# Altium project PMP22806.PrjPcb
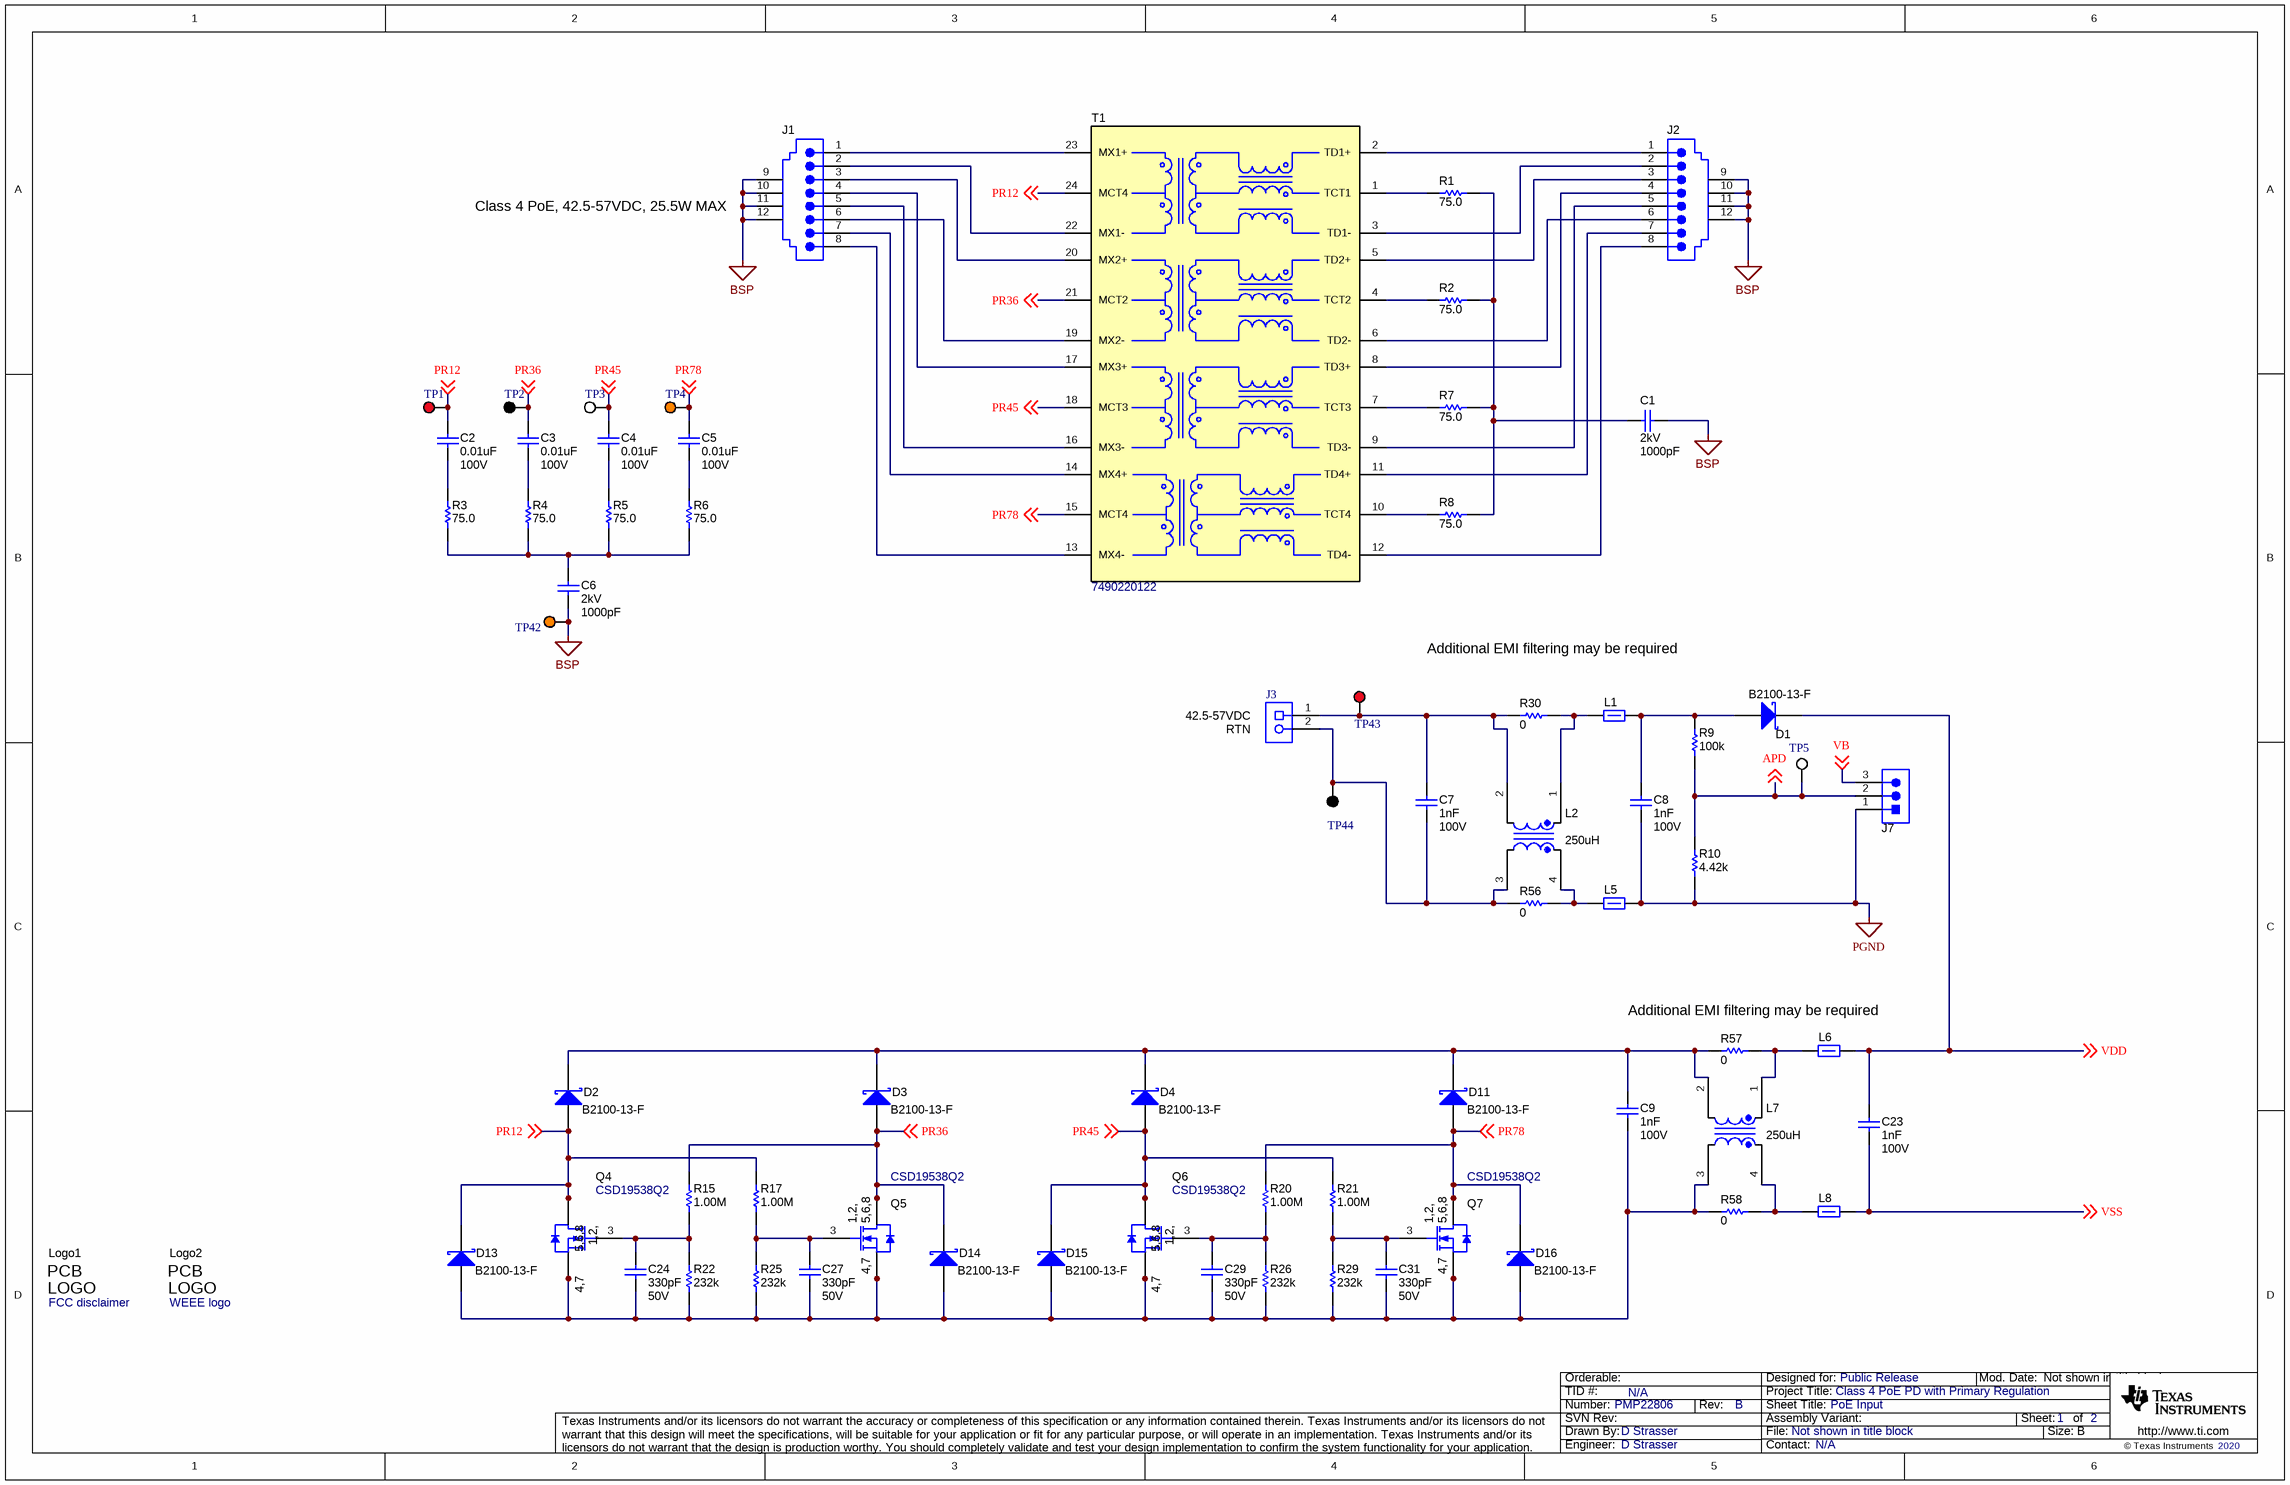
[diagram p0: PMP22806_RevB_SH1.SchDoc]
CopyrightYear: 2020; PCB_Layout: D Strasser; PCB_Rev: B; PRJ_Customer: Public Release; PRJ_Engineer: D Strasser; PRJ_Number: PMP22806; PRJ_Title: Class 4 PoE PD with Primary Regulation; SCH_Rev: B; TechSupport: N/A; TID: N/A
2 sheets, 196 parts. Net scope: global (net labels, ports and power ports of the same name join across sheets).
Board file: PMP22806_RevB.PcbDoc
Sheets:
  PMP22806_RevB_SH1.SchDoc
  PMP22806_RevB_SH2.SchDoc

## Sheet PMP22806_RevB_SH1.SchDoc: PoE Input
size 431 x 279 mm; Date: Not shown in title block; ApprovedBy: Not shown in title block; CheckedBy: Not shown in title block; Author: Not shown in title block; CompanyName: Not shown in title block; DrawnBy: D Strasser; Engineer: Not shown in title block; Organization: Not shown in title block; Address1: Not shown in title block; Address2: Not shown in title block; Address3: Not shown in title block; Address4: Not shown in title block; DocumentNumber: 1; Revision: Use project parameter SCH_Rev; SheetNumber: 1; SheetTotal: 2; PageSetup: Record=PageOptions¦CenterHorizontal=True¦CenterVertical=True¦PrintScale=1.00¦XCorrection=1.00¦YCorrection=1.00¦PrintKind=0¦BorderSize=5000000¦LeftOffset=0¦BottomOffset=0¦Orientation=2¦PaperLength=1000¦PaperWidth=1000¦Scale=100¦PaperSource=15¦PrintQuality=600¦MediaType=1¦DitherType=10¦PaperKind=Letter¦PrintScaleMode=1

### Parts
C1  VDC_V: 2kV  ValueDisplayed: 1000pF  [1812]  (hidden comment: GR443QR73D102KW01L)
C2  ValueDisplayed: 0.01uF  Value2: 100V  [0603L]  (hidden comment: Capacitor)
C3  ValueDisplayed: 0.01uF  Value2: 100V  [0603L]  (hidden comment: Capacitor)
C4  ValueDisplayed: 0.01uF  Value2: 100V  [0603L]  (hidden comment: Capacitor)
C5  ValueDisplayed: 0.01uF  Value2: 100V  [0603L]  (hidden comment: Capacitor)
C6  VDC_V: 2kV  ValueDisplayed: 1000pF  [1812]  (hidden comment: GR443QR73D102KW01L)
C7  Cap_F: 1nF  VDC_V: 100V  [0603]  (hidden comment: C1608X7R2A102K080AA)
C8  Cap_F: 1nF  VDC_V: 100V  [0603]  (hidden comment: C1608X7R2A102K080AA)
C9  Cap_F: 1nF  VDC_V: 100V  [0603]  (hidden comment: C1608X7R2A102K080AA)
C23  Cap_F: 1nF  VDC_V: 100V  [0603]  (hidden comment: C1608X7R2A102K080AA)
C24  ValueDisplayed: 330pF  VDC_V: 50V  [0603]  (hidden comment: GRM1885C1H331JA01D)
C27  ValueDisplayed: 330pF  VDC_V: 50V  [0603]  (hidden comment: GRM1885C1H331JA01D)
C29  ValueDisplayed: 330pF  VDC_V: 50V  [0603]  (hidden comment: GRM1885C1H331JA01D)
C31  ValueDisplayed: 330pF  VDC_V: 50V  [0603]  (hidden comment: GRM1885C1H331JA01D)
D1  PartNumber: B2100-13-F  [SMB]  (hidden comment: CMP-0028397-2)
D2  PartNumber: B2100-13-F  [SMB]  (hidden comment: CMP-0028397-2)
D3  PartNumber: B2100-13-F  [SMB]  (hidden comment: CMP-0028397-2)
D4  PartNumber: B2100-13-F  [SMB]  (hidden comment: CMP-0028397-2)
D11  PartNumber: B2100-13-F  [SMB]  (hidden comment: CMP-0028397-2)
D13  PartNumber: B2100-13-F  [SMB]  (hidden comment: CMP-0028397-2)
D14  PartNumber: B2100-13-F  [SMB]  (hidden comment: CMP-0028397-2)
D15  PartNumber: B2100-13-F  [SMB]  (hidden comment: CMP-0028397-2)
D16  PartNumber: B2100-13-F  [SMB]  (hidden comment: CMP-0028397-2)
J1  1-406541-1  [TEC_1-406541-1]  (value not drawn)
J2  1-406541-1  [TEC_1-406541-1]  (value not drawn)
J3  ED555/2DS  [TERM_BLK_ED555-2DS]  (value not drawn)
J7  TSW-103-07-G-S  [TSW-103-07-G-S]  (value not drawn)
L1  CMP-0003192-2  [0603]  (value not drawn)
L2  ValueDisplayed: 250uH  [WE-SL5]  (hidden comment: 744272251)
L5  CMP-0003192-2  [0603]  (value not drawn)
L6  CMP-0003192-2  [0603]  (value not drawn)
L7  ValueDisplayed: 250uH  [WE-SL5]  (hidden comment: 744272251)
L8  CMP-0003192-2  [0603]  (value not drawn)
Logo1  FCC disclaimer  [FCC_disclaimer]  (no BOM)
Logo2  WEEE logo  [WEEE_Minimum]  (no BOM)
Q4  CSD19538Q2  [DQK0006C]
Q5  CSD19538Q2  [DQK0006C]
Q6  CSD19538Q2  [DQK0006C]
Q7  CSD19538Q2  [DQK0006C]
R1  ValueDisplayed: 75.0  [0603L]  (hidden comment: Resistor)
R2  ValueDisplayed: 75.0  [0603L]  (hidden comment: Resistor)
R3  ValueDisplayed: 75.0  [0603L]  (hidden comment: Resistor)
R4  ValueDisplayed: 75.0  [0603L]  (hidden comment: Resistor)
R5  ValueDisplayed: 75.0  [0603L]  (hidden comment: Resistor)
R6  ValueDisplayed: 75.0  [0603L]  (hidden comment: Resistor)
R7  ValueDisplayed: 75.0  [0603L]  (hidden comment: Resistor)
R8  ValueDisplayed: 75.0  [0603L]  (hidden comment: Resistor)
R9  ValueDisplayed: 100k  [0603]  (hidden comment: CRCW0603100KFKEA)
R10  ValueDisplayed: 4.42k  [0603]  (hidden comment: CRCW06034K42FKEA)
R15  ValueDisplayed: 1.00M  [0603]  (hidden comment: CMP-0022138-4)
R17  ValueDisplayed: 1.00M  [0603]  (hidden comment: CMP-0022138-4)
R20  ValueDisplayed: 1.00M  [0603]  (hidden comment: CMP-0022138-4)
R21  ValueDisplayed: 1.00M  [0603]  (hidden comment: CMP-0022138-4)
R22  ValueDisplayed: 232k  [0603]  (hidden comment: CMP-0022224-4)
R25  ValueDisplayed: 232k  [0603]  (hidden comment: CMP-0022224-4)
R26  ValueDisplayed: 232k  [0603]  (hidden comment: CMP-0022224-4)
R29  ValueDisplayed: 232k  [0603]  (hidden comment: CMP-0022224-4)
R30  ValueDisplayed: 0  [0603]  (hidden comment: ERJ-3GEY0R00V)
R56  ValueDisplayed: 0  [0603]  (hidden comment: ERJ-3GEY0R00V)
R57  ValueDisplayed: 0  [0603]  (hidden comment: ERJ-3GEY0R00V)
R58  ValueDisplayed: 0  [0603]  (hidden comment: ERJ-3GEY0R00V)
T1  7490220122  [Wurth_7490220122]
TP1  5000  [Keystone5000]  (value not drawn)
TP2  5001  [Keystone5001]  (value not drawn)
TP3  5002  [Keystone5002]  (value not drawn)
TP4  5003  [Keystone5003]  (value not drawn)
TP5  5002  [Keystone5002]  (value not drawn)
TP42  5003  [Keystone5003]  (value not drawn)
TP43  5000  [Keystone5000]  (value not drawn)
TP44  5001  [Keystone5001]  (value not drawn)

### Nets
BSP: C1.1 C6.2 J1.9 J1.10 J1.11 J1.12 J2.9 J2.10 J2.11 J2.12 TP42.1
PGND: C8.2 J7.1 L5.2 R10.1
APD: J7.2 R9.1 R10.2 TP5.1 ; off-sheet APD
PR12: C2.1 D2.2(A) D13.1(K) Q4.1(D) Q4.2(D) Q4.5(D) Q4.6(D) Q4.8(D) R17.2 T1.24(MCT4) TP1.1 ; off-sheet PR12
PR36: C3.1 D3.2(A) D14.1(K) Q5.1(D) Q5.2(D) Q5.5(D) Q5.6(D) Q5.8(D) R15.2 T1.21(MCT2) TP2.1 ; off-sheet PR36
PR45: C4.1 D4.2(A) D15.1(K) Q6.1(D) Q6.2(D) Q6.5(D) Q6.6(D) Q6.8(D) R21.2 T1.18(MCT3) TP3.1 ; off-sheet PR45
PR78: C5.1 D11.2(A) D16.1(K) Q7.1(D) Q7.2(D) Q7.5(D) Q7.6(D) Q7.8(D) R20.2 T1.15(MCT4) TP4.1 ; off-sheet PR78
VB: J7.3 ; off-sheet VB
VDD: C23.1 D1.1(K) L6.2 ; off-sheet VDD
VSS: C23.2 L8.2 ; off-sheet VSS
NetC1_2: C1.2 R1.2 R2.2 R7.2 R8.1
NetC2_2: C2.2 R3.2
NetC3_2: C3.2 R4.2
NetC4_2: C4.2 R5.2
NetC5_2: C5.2 R6.2
NetC6_1: C6.1 R3.1 R4.1 R5.1 R6.1
NetC7_1: C7.1 J3.1 L2.2 R30.1 TP43.1
NetC7_2: C7.2 J3.2 L2.3 R56.1 TP44.1
NetC8_1: C8.1 D1.2(A) L1.2 R9.2
NetC9_1: C9.1 D2.1(K) D3.1(K) D4.1(K) D11.1(K) L7.2 R57.1
NetC9_2: C9.2 C24.2 C27.2 C29.2 C31.2 D13.2(A) D14.2(A) D15.2(A) D16.2(A) L7.3 Q4.4(S) Q4.7(S) Q5.4(S) Q5.7(S) Q6.4(S) Q6.7(S) Q7.4(S) Q7.7(S) R22.1 R25.1 R26.1 R29.1 R58.1
NetC24_1: C24.1 Q4.3(G) R15.1 R22.2
NetC27_1: C27.1 Q5.3(G) R17.1 R25.2
NetC29_1: C29.1 Q6.3(G) R20.1 R26.2
NetC31_1: C31.1 Q7.3(G) R21.1 R29.2
NetJ1_1: J1.1 T1.23(MX1+)
NetJ1_2: J1.2 T1.22(MX1-)
NetJ1_3: J1.3 T1.20(MX2+)
NetJ1_4: J1.4 T1.17(MX3+)
NetJ1_5: J1.5 T1.16(MX3-)
NetJ1_6: J1.6 T1.19(MX2-)
NetJ1_7: J1.7 T1.14(MX4+)
NetJ1_8: J1.8 T1.13(MX4-)
NetJ2_1: J2.1 T1.2(TD1+)
NetJ2_2: J2.2 T1.3(TD1-)
NetJ2_3: J2.3 T1.5(TD2+)
NetJ2_4: J2.4 T1.8(TD3+)
NetJ2_5: J2.5 T1.9(TD3-)
NetJ2_6: J2.6 T1.6(TD2-)
NetJ2_7: J2.7 T1.11(TD4+)
NetJ2_8: J2.8 T1.12(TD4-)
NetL1_1: L1.1 L2.1 R30.2
NetL2_4: L2.4 L5.1 R56.2
NetL6_1: L6.1 L7.1 R57.2
NetL7_4: L7.4 L8.1 R58.2
NetR1_1: R1.1 T1.1(TCT1)
NetR2_1: R2.1 T1.4(TCT2)
NetR7_1: R7.1 T1.7(TCT3)
NetR8_2: R8.2 T1.10(TCT4)

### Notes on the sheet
- Class 4 PoE, 42.5-57VDC, 25.5W MAX
- Additional EMI filtering may be required
- (near J3) 42.5-57VDC
- (near J3) RTN

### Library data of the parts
C1 C6 = CMP-0009438-2: CAP, CERM, 1000 pF, 2000 V, +/- 10%, X7R, 1812; Manufacturer: MuRata; TaMin_C: -55°C; Polarized: N; SizeAreaWB_mm2: 23.1; Value1: Unknown; U/M: EA; Value: 1000pF; TaMax_C: 125°C; SizeZ_mm: 1.35; SizeX_mm: 4.5; SizeY_mm: 3.2; Value2: 2000V; SizeArea_mm2: 14.4; Cap_F: 1nF; AEC Category: Q200
C2-C5 = CMP-0007468-5: CAP, CERM, 0.01 uF, 100 V, +/- 10%, X7R, 0603; PartNumber: GRM188R72A103KA01D; Manufacturer: MuRata; Polarized: N; Value: 0.01uF; U/M: EA; Cap_F: 10nF; Value1: Unknown; TaMin_C: -55°C; TaMax_C: 125°C; Cap_Case: 0603; SizeArea_mm2: 1.28; SizeAreaWB_mm2: 4.68; SizeX_mm: 1.6; SizeY_mm: 0.8; SizeZ_mm: 1; AEC Category: Q200
C7-C9 C23 = CMP-0007053-4: CAP, CERM, 1000 pF, 100 V, +/- 10%, X7R, 0603; Manufacturer: TDK; Polarized: N; Value: 1000pF; U/M: EA; Value1: Unknown; TaMin_C: -55°C; TaMax_C: 125°C; SizeAreaWB_mm2: 4.68; SizeZ_mm: 1; SizeX_mm: 1.6; SizeY_mm: 0.8; SizeArea_mm2: 1.28; AEC Category: Q200
C24 C27 C29 C31 = CMP-0007209-4: CAP, CERM, 330 pF, 50 V, +/- 5%, C0G/NP0, 0603; Manufacturer: MuRata; Polarized: N; Value: 330pF; U/M: EA; Value1: Unknown; TaMin_C: -55°C; TaMax_C: 125°C; AEC Category: Q200; SizeAreaWB_mm2: 4.68; SizeZ_mm: 1; SizeX_mm: 1.6; SizeY_mm: 0.8; SizeArea_mm2: 1.28
D1-D4 D11 D13-D16 = CMP-0028397-2: Diode, Schottky, 100 V, 2 A, SMB; Manufacturer: Diodes Inc.; Vf_V: 790mV; Value: 100V; Value1: 2A; Value2: 0.79V; TJmax_C: 150°C; RJC_CperW: 15; SizeArea_mm2: 21.336; Green_REACh: Passed; Green_Lifecycle: Active; SizeY_mm: 3.81; AEC Category: Q101; SizeZ_mm: 2.6; SizeAreaWB_mm2: 44.156; SizeX_mm: 5.6
J1 J2 = CMP-0054918-1: RJ45, No LED, tab up, R/A, TH; Manufacturer: TE Connectivity; CNHeader: FALSE; Green_Lifecycle: Active; Green_REACh: Passed; ContactFinish: Gold; CT: TRUE
J3 = CMP-0074913-1: Terminal Block, 3.5mm Pitch, 2x1, TH; Manufacturer: On-Shore Technology; Cert_VDE: Y; CNHeader: False; Current_A: 6A; Green_Lifecycle: Active; Shrouded: N; Gender: Female; Green_REACh: Passed; Voltage_V: 150V; Row_Count: 1; Pitch_mm: 3.5; ContactFinish: Brass; CT: True
J7 = CMP-0075407-2: Header, 100mil, 3x1, Gold, TH; Manufacturer: Samtec; Pitch_mm: 2.54; Cert_VDE: N; Gender: Male; Cert_CSA: Y; Voltage_V: 550V; Green_REACh: Passed; Current_A: 6.3A; Green_Lifecycle: Active; Row_Count: 1
L1 L5 L6 L8 = CMP-0003192-2: Ferrite Bead, 300 ohm @ 100 MHz, 2 A, 0603; PartNumber: 742792641; Manufacturer: Wurth Elektronik; Value: 300 ohm; Imax_A: 2A; DCR_ohm: 0.15; Value1: 0.15 ohm; ZTyp@100MHz_Ohm: 300; Ztyp@1GHz_Ohm: 273.989; SizeAreaWB_mm2: 4.68; SizeZ_mm: 1; SizeX_mm: 1.6; SizeY_mm: 0.8; SizeArea_mm2: 1.28
L2 L7 = CMP-0013220-2: Coupled inductor, 250 uH,  A, 0.035 ohm, SMD; Manufacturer: Wurth Elektronik; DCR_ohm: 0.035; Value: 250uH; Ind_H: 250µH
Logo1 = CMP-0074847-1: FCC_disclaimer
Logo2 = CMP-0074769-1
Q4-Q7 = CMP-0000968-2: MOSFET, N-CH, 100 V, 4.5 A, DQK0006C (WSON-6); Alternate Manufacturer: None; Manufacturer: Texas Instruments; SizeZ_mm: 0.8; ChType: N; VdsMax_V: 100V; SizeX_mm: 2; SizeAreaWB_mm2: 9; Vgs_V: 20V; Value: 100V; SizeArea_mm2: 4; AEC Category: Q101; IdsMax_A: 4.5A; U/M: EA
R1-R8 = CMP-0022590-4: RES, 75.0, 1%, 0.1 W, AEC-Q200 Grade 0, 0603; PartNumber: CRCW060375R0FKEA; Manufacturer: Vishay-Dale; Value: 75.0; Res_ohm: 75; Value_Code: 75R0; Power_W: 100mW; Value2: 0.1W; VDC_V: 75V; TempCo: 100 ppm/C; SizeArea_mm2: 1.28; SizeX_mm: 1.6; SizeY_mm: 0.8; SizeZ_mm: 1; EIA_Code: E96; AEC Category: Q200; AEC Qualified: Y; AEC Grade: 0
R9 = CMP-0021990-4: RES, 100 k, 1%, 0.1 W, AEC-Q200 Grade 0, 0603; Manufacturer: Vishay-Dale; Power_W: 100mW; TempCo: 100 ppm/C; Value: 100k; EIA_Code: E96; SizeX_mm: 1.6; SizeY_mm: 0.8; SizeZ_mm: 1; Value2: 0.1W; SizeArea_mm2: 1.28; AEC Qualified: Y; VDC_V: 75V; AEC Category: Q200; AEC Grade: 0
R10 = CMP-0022453-4: RES, 4.42 k, 1%, 0.1 W, AEC-Q200 Grade 0, 0603; Manufacturer: Vishay-Dale; Power_W: 100mW; TempCo: 100 ppm/C; Value_Code: 4k42; Value: 4.42k; EIA_Code: E96; SizeX_mm: 1.6; SizeY_mm: 0.8; SizeZ_mm: 1; Value2: 0.1W; SizeArea_mm2: 1.28; AEC Qualified: Y; VDC_V: 75V; AEC Category: Q200; AEC Grade: 0
R15 R17 R20 R21 = CMP-0022138-4: RES, 1.00 M, 1%, 0.1 W, AEC-Q200 Grade 0, 0603; PartNumber: CRCW06031M00FKEA; Manufacturer: Vishay-Dale; Value: 1.00Meg; Res_ohm: 1M; Value_Code: 1M00; Power_W: 100mW; Value2: 0.1W; VDC_V: 75V; TempCo: 100 ppm/C; EIA_Code: E96; AEC Category: Q200; AEC Qualified: Y; AEC Grade: 0; SizeX_mm: 1.6; SizeY_mm: 0.8; SizeZ_mm: 1; SizeArea_mm2: 1.28
R22 R25 R26 R29 = CMP-0022224-4: RES, 232 k, 1%, 0.1 W, AEC-Q200 Grade 0, 0603; PartNumber: CRCW0603232KFKEA; Manufacturer: Vishay-Dale; Value: 232k; Power_W: 100mW; Value2: 0.1W; VDC_V: 75V; TempCo: 100 ppm/C; EIA_Code: E96; AEC Category: Q200; AEC Qualified: Y; AEC Grade: 0; SizeX_mm: 1.6; SizeY_mm: 0.8; SizeZ_mm: 1; SizeArea_mm2: 1.28
R30 R56-R58 = CMP-0025874-4: RES, 0, 5%, 0.1 W, AEC-Q200 Grade 0, 0603; Manufacturer: Panasonic; Power_W: 100mW; TempCo: 600 ppm/C; Value_Code: 0000; Value: 0; EIA_Code: E24; SizeX_mm: 1.6; SizeY_mm: 0.8; SizeZ_mm: 1; Value2: 0.1W; SizeArea_mm2: 1.28; AEC Qualified: Y; VDC_V: 50V; AEC Category: Q200; SizeAreaWB_mm2: 4.68
T1 = CMP-0030597-1: Transformer, 350 uH, SMT; Manufacturer: Wurth Elektronik; Value: 350uH; Ind_H: 350µH; Lp: 350
TP1 TP43 = CMP-0055137-1: Test Point, Miniature, Red, TH; Manufacturer: Keystone; CNHeader: FALSE; Green_Lifecycle: Active; Green_REACh: Passed; ContactFinish: Silver; CT: TRUE
TP2 TP44 = CMP-0055138-1: Test Point, Miniature, Black, TH; Manufacturer: Keystone; CNHeader: FALSE; Green_Lifecycle: Active; Green_REACh: Passed; ContactFinish: Silver; CT: TRUE
TP3 TP5 = CMP-0055139-1: Test Point, Miniature, White, TH; Manufacturer: Keystone; CNHeader: FALSE; Green_Lifecycle: Active; Green_REACh: Passed; ContactFinish: Silver; CT: TRUE
TP4 TP42 = CMP-0055140-1: Test Point, Miniature, Orange, TH; Manufacturer: Keystone; CNHeader: FALSE; Green_Lifecycle: Active; Green_REACh: Passed; ContactFinish: Silver; CT: TRUE

## Sheet PMP22806_RevB_SH2.SchDoc: Flyback Converter
size 431 x 279 mm; Date: Not shown in title block; ApprovedBy: Not shown in title block; CheckedBy: Not shown in title block; Author: Not shown in title block; CompanyName: Not shown in title block; DrawnBy: D Strasser; Engineer: Not shown in title block; Organization: Not shown in title block; Address1: Not shown in title block; Address2: Not shown in title block; Address3: Not shown in title block; Address4: Not shown in title block; DocumentNumber: 2; Revision: Use project parameter SCH_Rev; SheetNumber: 2; SheetTotal: 2; PageSetup: Record=PageOptions¦CenterHorizontal=True¦CenterVertical=True¦PrintScale=1.00¦XCorrection=1.00¦YCorrection=1.00¦PrintKind=0¦BorderSize=5000000¦LeftOffset=0¦BottomOffset=0¦Orientation=2¦PaperLength=1000¦PaperWidth=1000¦Scale=100¦PaperSource=15¦PrintQuality=600¦MediaType=1¦DitherType=10¦PaperKind=Letter¦PrintScaleMode=1
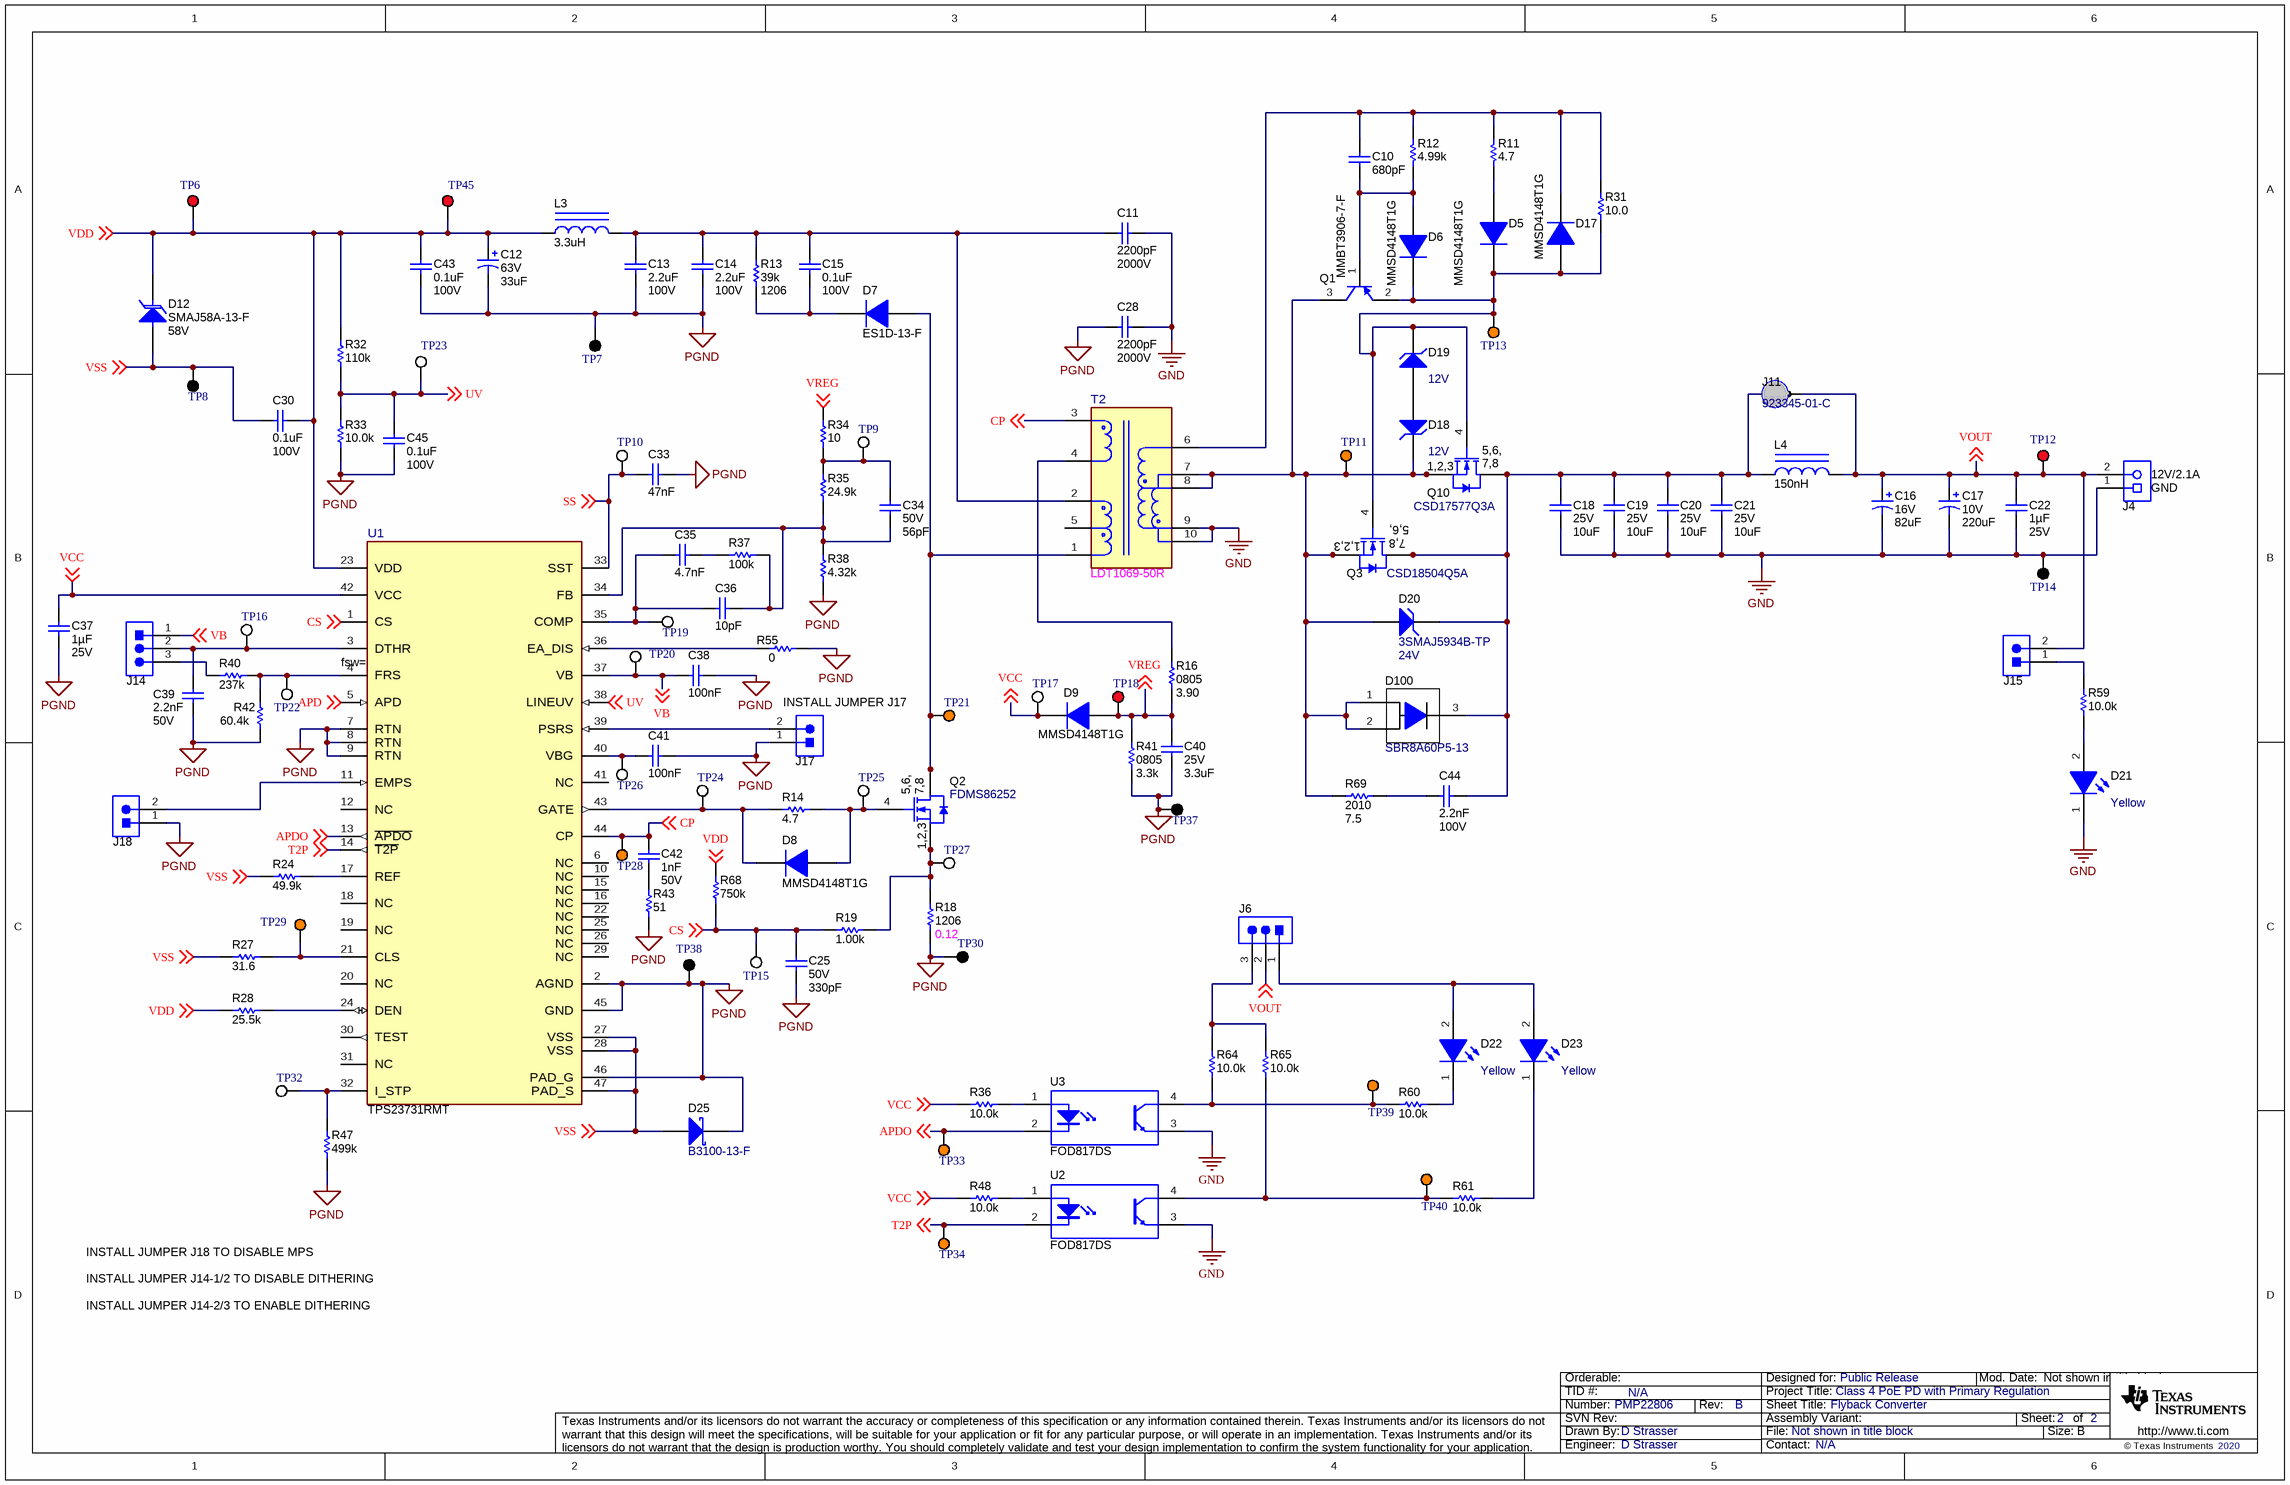
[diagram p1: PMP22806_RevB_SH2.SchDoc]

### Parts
C10  ValueDisplayed: 680pF  [0603L]  (hidden comment: GRM188R71H681KA01D)
C11  ValueDisplayed: 2200pF  Value2: 2000V  [1812_HV]  (hidden comment: Capacitor)
C12  VDC_V: 63V  ValueDisplayed: 33uF  [SM_RADIAL_F]  (hidden comment: EEE-FK1J330P)
C13  ValueDisplayed: 2.2uF  Value2: 100V  [1210_270]  (hidden comment: Capacitor)
C14  ValueDisplayed: 2.2uF  Value2: 100V  [1210_270]  (hidden comment: Capacitor)
C15  ValueDisplayed: 0.1uF  Value2: 100V  [0805_HV]  (hidden comment: Capacitor)
C16  VDC_V: 16V  ValueDisplayed: 82uF  [SM_RADIAL_8MM]  (hidden comment: 16SVP82M)
C17  VDC_V: 10V  ValueDisplayed: 220uF  [7343-30]  (hidden comment: 10TPE220ML)
C18  VDC_V: 25V  ValueDisplayed: 10uF  [1210_220]  (hidden comment: 885012209028)
C19  VDC_V: 25V  ValueDisplayed: 10uF  [1210_220]  (hidden comment: 885012209028)
C20  VDC_V: 25V  ValueDisplayed: 10uF  [1210_220]  (hidden comment: 885012209028)
C21  VDC_V: 25V  ValueDisplayed: 10uF  [1210_220]  (hidden comment: 885012209028)
C22  Cap_F: 1µF  VDC_V: 25V  [0603]  (hidden comment: 885012206076)
C25  VDC_V: 50V  ValueDisplayed: 330pF  [0603]  (hidden comment: GRM1885C1H331JA01D)
C28  ValueDisplayed: 2200pF  Value2: 2000V  [1812_HV]  (hidden comment: Capacitor)
C30  ValueDisplayed: 0.1uF  Value2: 100V  [0805_HV]  (hidden comment: Capacitor)
C33  Cap_F: 47nF  [0603]  (hidden comment: GRM188R71E473KA01D)
C34  VDC_V: 50V  ValueDisplayed: 56pF  [0603]  (hidden comment: 06035A560FAT2A)
C35  Cap_F: 4.7nF  [0603]  (hidden comment: 885012206087)
C36  ValueDisplayed: 10pF  [0603]  (hidden comment: 06035A100JAT2A)
C37  Cap_F: 1µF  VDC_V: 25V  [0603]  (hidden comment: 885012206076)
C38  Cap_F: 100nF  [0603]  (hidden comment: 885012206071)
C39  Cap_F: 2.2nF  VDC_V: 50V  [0603]  (hidden comment: C0603C222K5RAC)
C40  VDC_V: 25V  ValueDisplayed: 3.3uF  [1206_180]  (hidden comment: GRM31CR71E335KA88L)
C41  Cap_F: 100nF  [0603]  (hidden comment: 885012206071)
C42  Cap_F: 1nF  VDC_V: 50V  [0603]  (hidden comment: 885012206083)
C43  ValueDisplayed: 0.1uF  Value2: 100V  [0805_HV]  (hidden comment: Capacitor)
C44  Cap_F: 2.2nF  VDC_V: 100V  [0603]  (hidden comment: 06031C222KAT2A)
C45  ValueDisplayed: 0.1uF  Value2: 100V  [0805_HV]  (hidden comment: Capacitor)
D5  MMSD4148T1G  [SOD-123]
D6  MMSD4148T1G  [SOD-123]
D7  ES1D-13-F  [SMA]
D8  MMSD4148T1G  [SOD-123]
D9  MMSD4148T1G  [SOD-123]
D12  SMAJ58A-13-F  value 58V  [SMA]
D17  MMSD4148T1G  [SOD-123]
D18  value 12V  [SOD-123]  (hidden comment: MMSZ5242B-7-F)
D19  value 12V  [SOD-123]  (hidden comment: MMSZ5242B-7-F)
D20  3SMAJ5934B-TP  value 24V  [SMA]
D21  value Yellow  [WL-SMCW_YELLOW]  (hidden comment: 150060YS75000)
D22  value Yellow  [WL-SMCW_YELLOW]  (hidden comment: 150060YS75000)
D23  value Yellow  [WL-SMCW_YELLOW]  (hidden comment: 150060YS75000)
D25  B3100-13-F  [SMC]
D100  SBR8A60P5-13  [POWERDI5]
J4  Receptacle_2x1  [TERM_BLK_ED555-2DS]  (value not drawn)
J6  TSW-103-07-G-S  [TSW-103-07-G-S]  (value not drawn)
J11  923345-01-C  [3M_923345-01-C]
J14  TSW-103-07-G-S  [TSW-103-07-G-S]  (value not drawn)
J15  TSW-102-07-G-S  [TSW-102-07-G-S]  (value not drawn)
J17  TSW-102-07-G-S  [TSW-102-07-G-S]  (value not drawn)
J18  TSW-102-07-G-S  [TSW-102-07-G-S]  (value not drawn)
L3  ValueDisplayed: 3.3uH  [WE-TPC-M1]  (hidden comment: 744042003)
L4  ValueDisplayed: 150nH  [WE-HCM_7050]  (hidden comment: 744302015)
Q1  MMBT3906-7-F  [SOT-23L]
Q2  FDMS86252  [TRANS_Fairchild_PQFN08A]
Q3  CSD18504Q5A  [DQJ0008A]
Q10  CSD17577Q3A  [DNH0008A]
R11  ValueDisplayed: 4.7  [0603L]  (hidden comment: Resistor)
R12  ValueDisplayed: 4.99k  [0603L]  (hidden comment: CRCW06034K99FKEA)
R13  ValueDisplayed: 39k  PackageReference: 1206  [1206L]  (hidden comment: Resistor)
R14  ValueDisplayed: 4.7  [0603]  (hidden comment: CRCW06034R70JNEA)
R16  PackageReference: 0805  ValueDisplayed: 3.90  [0805_HV]  (hidden comment: ERJ-6RQF3R9V)
R18  ValueDisplayed: 0.12  [1206]  (hidden comment: ERJ-8RQFR12V)
R19  ValueDisplayed: 1.00k  [0603]  (hidden comment: RC0603FR-071KL)
R24  ValueDisplayed: 49.9k  [0603]  (hidden comment: CRCW060349K9FKEA)
R27  ValueDisplayed: 31.6  [0805_HV]  (hidden comment: CRCW080531R6FKEA)
R28  ValueDisplayed: 25.5k  [0603]  (hidden comment: RC0603FR-0725K5L)
R31  ValueDisplayed: 10.0  [0603]  (hidden comment: CRCW060310R0FKEA)
R32  ValueDisplayed: 110k  [0603]  (hidden comment: CRCW0603110KFKEA)
R33  ValueDisplayed: 10.0k  [0603L]  (hidden comment: CRCW060310K0FKEA)
R34  ValueDisplayed: 10  [0603]  (hidden comment: CRCW060310R0JNEA)
R35  ValueDisplayed: 24.9k  [0603]  (hidden comment: RC0603FR-0724K9L)
R36  ValueDisplayed: 10.0k  [0603L]  (hidden comment: CRCW060310K0FKEA)
R37  ValueDisplayed: 100k  [0603]  (hidden comment: CRCW0603100KFKEA)
R38  ValueDisplayed: 4.32k  [0603]  (hidden comment: CRCW06034K32FKEA)
R40  ValueDisplayed: 237k  [0603]  (hidden comment: RC0603FR-07237KL)
R41  PackageReference: 0805  ValueDisplayed: 3.3k  [0805_HV]  (hidden comment: CRCW08053K30JNEA)
R42  ValueDisplayed: 60.4k  [0603]  (hidden comment: CRCW060360K4FKEA)
R43  ValueDisplayed: 51  [1206]  (hidden comment: CRCW120651R0JNEA)
R47  ValueDisplayed: 499k  [0603]  (hidden comment: CRCW0603499KFKEA)
R48  ValueDisplayed: 10.0k  [0603L]  (hidden comment: CRCW060310K0FKEA)
R55  ValueDisplayed: 0  [0603]  (hidden comment: ERJ-3GEY0R00V)
R59  ValueDisplayed: 10.0k  [0603L]  (hidden comment: CRCW060310K0FKEA)
R60  ValueDisplayed: 10.0k  [0603L]  (hidden comment: CRCW060310K0FKEA)
R61  ValueDisplayed: 10.0k  [0603L]  (hidden comment: CRCW060310K0FKEA)
R64  ValueDisplayed: 10.0k  [0603L]  (hidden comment: CRCW060310K0FKEA)
R65  ValueDisplayed: 10.0k  [0603L]  (hidden comment: CRCW060310K0FKEA)
R68  ValueDisplayed: 750k  [0603]  (hidden comment: CRCW0603750KFKEA)
R69  ValueDisplayed: 7.5  [2010]  (hidden comment: CRCW20107R50JNEF)
T2  PartNumber: LDT1069-50R  [FP-LDT1038-50R_SMD10-MFG]  (hidden comment: LDT1038-50R)
TP6  5000  [Keystone5000]  (value not drawn)
TP7  5001  [Keystone5001]  (value not drawn)
TP8  5001  [Keystone5001]  (value not drawn)
TP9  5002  [Keystone5002]  (value not drawn)
TP10  5002  [Keystone5002]  (value not drawn)
TP11  5003  [Keystone5003]  (value not drawn)
TP12  5000  [Keystone5000]  (value not drawn)
TP13  5003  [Keystone5003]  (value not drawn)
TP14  5001  [Keystone5001]  (value not drawn)
TP15  5002  [Keystone5002]  (value not drawn)
TP16  5002  [Keystone5002]  (value not drawn)
TP17  5002  [Keystone5002]  (value not drawn)
TP18  5000  [Keystone5000]  (value not drawn)
TP19  5002  [Keystone5002]  (value not drawn)
TP20  5002  [Keystone5002]  (value not drawn)
TP21  5003  [Keystone5003]  (value not drawn)
TP22  5002  [Keystone5002]  (value not drawn)
TP23  5002  [Keystone5002]  (value not drawn)
TP24  5002  [Keystone5002]  (value not drawn)
TP25  5002  [Keystone5002]  (value not drawn)
TP26  5002  [Keystone5002]  (value not drawn)
TP27  5002  [Keystone5002]  (value not drawn)
TP28  5003  [Keystone5003]  (value not drawn)
TP29  5003  [Keystone5003]  (value not drawn)
TP30  5001  [Keystone5001]  (value not drawn)
TP32  5002  [Keystone5002]  (value not drawn)
TP33  5003  [Keystone5003]  (value not drawn)
TP34  5003  [Keystone5003]  (value not drawn)
TP37  5001  [Keystone5001]  (value not drawn)
TP38  5001  [Keystone5001]  (value not drawn)
TP39  5003  [Keystone5003]  (value not drawn)
TP40  5003  [Keystone5003]  (value not drawn)
TP45  5000  [Keystone5000]  (value not drawn)
U1  TPS23731RMT  [RMT0045A-MFG]
U2  FOD817DS  [N04C]
U3  FOD817DS  [N04C]

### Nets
GND: C11.1 C16.2(-) C17.2(-) C18.2 C19.2 C20.2 C21.2 C22.2 C28.1 D21.1(K) J4.1 T2.9 T2.10 TP14.1 U2.3(E) U3.3(E)
PGND: C12.2(-) C13.2 C14.2 C25.2 C28.2 C33.1 C37.2 C38.1 C39.2 C40.2 C41.1 C43.2 C45.1 D25.1(K) J17.1 J18.1 R18.2 R33.2 R38.2 R41.1 R42.1 R43.1 R47.1 R55.2 TP7.1 TP30.1 TP37.1 TP38.1 U1.2(AGND) U1.7(RTN) U1.8(RTN) U1.9(RTN) U1.45(GND) U1.46(PAD_G)
APD: U1.5(APD) ; off-sheet APD
APDO: TP33.1 U1.13(~{APDO}) U3.2(K) ; off-sheet APDO
CP: C42.1 T2.3 TP28.1 U1.44(CP) ; off-sheet CP
CS: C25.1 R19.1 R68.2 TP15.1 U1.1(CS) ; off-sheet CS
SS: C33.2 TP10.1 U1.33(SST) ; off-sheet SS
T2P: TP34.1 U1.14(~{T2P}) U2.2(K) ; off-sheet T2P
UV: C45.2 R32.1 R33.1 TP23.1 U1.38(LINEUV) ; off-sheet UV
VB: C38.2 J14.1 TP20.1 U1.37(VB) ; off-sheet VB
VCC: C37.1 D9.1(K) R36.2 R48.2 TP17.1 U1.42(VCC) ; off-sheet VCC
VDD: C12.1(+) C30.1 C43.1 D12.1(K) L3.1 R28.1 R32.2 R68.1 TP6.1 TP45.1 U1.23(VDD) ; off-sheet VDD
VOUT: C16.1(+) C17.1(+) C22.1 J4.2 J6.2 J11.2 J15.2 L4.2 TP12.1 ; off-sheet VOUT
VREG: C40.1 D9.2(A) R16.1 R34.1 R41.2 TP18.1 ; off-sheet VREG
VSS: C30.2 D12.2(A) D25.2(A) R24.1 R27.1 TP8.1 U1.27(VSS) U1.28(VSS) U1.47(PAD_S) ; off-sheet VSS
NetC10_1: C10.1 D17.1(K) R11.1 R12.2 R31.2 T2.6
NetC10_2: C10.2 D6.2(A) Q1.1(B) R12.1
NetC11_2: C11.2 C13.1 C14.1 C15.2 L3.2 R13.2 T2.2
NetC15_1: C15.1 D7.1(K) R13.1
NetC18_1: C18.1 C19.1 C20.1 C21.1 C44.1 D20.1(K) D100.3(K) J11.1 L4.1 Q3.5(D) Q3.6(D) Q3.7(D) Q3.8(D) Q3.9(D) Q10.5(D) Q10.6(D) Q10.7(D) Q10.8(D) Q10.9(D)
NetC34_1: C34.1 R34.2 R35.2 TP9.1
NetC34_2: C34.2 C36.1 R35.1 R37.2 R38.1 U1.34(FB)
NetC35_1: C35.1 R37.1
NetC35_2: C35.2 C36.2 TP19.1 U1.35(COMP)
NetC39_1: C39.1 J14.2 TP16.1 U1.3(DTHR)
NetC41_2: C41.2 TP26.1 U1.40(VBG)
NetC42_2: C42.2 R43.2
NetC44_2: C44.2 R69.2
NetD5_1: D5.1(K) D6.1(K) D17.2(A) D19.1(K) Q1.2(E) Q3.4(G) Q10.4(G) R31.1 TP13.1
NetD5_2: D5.2(A) R11.2
NetD7_2: D7.2(A) Q2.5(D) Q2.6(D) Q2.7(D) Q2.8(D) T2.1 TP21.1
NetD8_1: D8.1(K) R14.1 TP24.1 U1.43(GATE)
NetD8_2: D8.2(A) Q2.4(G) R14.2 TP25.1
NetD18_1: D18.1(K) D20.2(A) D100.1(A) D100.2(A) Q1.3(C) Q3.1(S) Q3.2(S) Q3.3(S) Q10.1(S) Q10.2(S) Q10.3(S) R69.1 T2.7 T2.8 TP11.1
NetD18_2: D18.2(A) D19.2(A)
NetD21_2: D21.2(A) R59.1
NetD22_1: D22.1(K) R60.2
NetD22_2: D22.2(A) D23.2(A) J6.1
NetD23_1: D23.1(K) R61.2
NetJ6_3: J6.3 R64.2 R65.2
NetJ14_3: J14.3 R40.1
NetJ15_1: J15.1 R59.2
NetJ17_2: J17.2 U1.39(PSRS)
NetJ18_2: J18.2 U1.11(EMPS)
NetQ2_1: Q2.1(S) Q2.2(S) Q2.3(S) R18.1 R19.2 TP27.1
NetR16_2: R16.2 T2.4
NetR24_2: R24.2 U1.17(REF)
NetR27_2: R27.2 TP29.1 U1.21(CLS)
NetR28_2: R28.2 U1.24(DEN)
NetR36_1: R36.1 U3.1(A)
NetR40_2: R40.2 R42.2 TP22.1 U1.4(FRS)
NetR47_2: R47.2 TP32.1 U1.32(I_STP)
NetR48_1: R48.1 U2.1(A)
NetR55_1: R55.1 U1.36(EA_DIS)
NetR60_1: R60.1 R64.1 TP39.1 U3.4(C)
NetR61_1: R61.1 R65.1 TP40.1 U2.4(C)

Not connected (* = marked no-connect by the designer): T2 5; U1 6(NC) 10(NC) 12(NC) 15(NC) 16(NC) 18(NC) 19(NC) 20(NC) 22(NC) 25(NC) 26(NC) 29(NC) 30(TEST) 31(NC) 41(NC)

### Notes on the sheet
- (near J4) GND
- (near J4) 12V/2.1A
- fsw=250KHz
- (near J17) INSTALL JUMPER J17
- INSTALL JUMPER J18 TO DISABLE MPS
- INSTALL JUMPER J14-1/2 TO DISABLE DITHERING
- INSTALL JUMPER J14-2/3 TO ENABLE DITHERING

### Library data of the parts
C10 = CMP-0007461-4: CAP, CERM, 680 pF, 50 V, +/- 10%, X7R, 0603; Manufacturer: MuRata; TaMin_C: -55°C; Polarized: N; SizeAreaWB_mm2: 4.68; Value1: Unknown; U/M: EA; Value: 680pF; TaMax_C: 125°C; SizeZ_mm: 1; SizeX_mm: 1.6; SizeY_mm: 0.8; Cap_Case: 0603; Value2: 50V; SizeArea_mm2: 1.28; CompType: Capacitor; AEC Category: Q200
C11 C28 = CMP-0009358-2: CAP, CERM, 2200 pF, 2000 V, +/- 10%, X7R, 1812; PartNumber: C4532X7R3D222K130KA; Manufacturer: TDK; Polarized: N; Value: 2200pF; U/M: EA; Cap_F: 2.2nF; Value1: Unknown; VDC_V: 2kV; TaMin_C: -55°C; TaMax_C: 125°C; Cap_Case: 1812; SizeArea_mm2: 14.4; SizeAreaWB_mm2: 23.1; SizeX_mm: 4.5; SizeY_mm: 3.2; SizeZ_mm: 1.35; AEC Category: Q200
C12 = CMP-0011191-2: CAP, AL, 33 uF, 63 V, +/- 20%, 0.65 ohm, AEC-Q200 Grade 2, SMD; Manufacturer: Panasonic; TaMin_C: -55°C; ESR_ohm: 0.65; Polarized: Y; SizeAreaWB_mm2: 123.6; U/M: EA; Value: 33uF; TaMax_C: 105°C; SizeZ_mm: 10.2; SizeX_mm: 10; SizeY_mm: 8.3; Cap_Case: F; SizeArea_mm2: 83; CompType: Capacitor; Cap_F: 33µF; IRMS_A: 250mA; AEC Grade: 2; AEC Category: Q200
C13 C14 = CMP-0009232-2: CAP, CERM, 2.2 uF, 100 V, +/- 10%, X7R, 1210; PartNumber: GRM32ER72A225KA35L; Manufacturer: MuRata; Polarized: N; Value: 2.2uF; U/M: EA; Cap_F: 2.2µF; ESR_ohm: 7m; Value1: 0.007 ohm; IRMS_A: 4.4A; TaMin_C: -55°C; TaMax_C: 125°C; Cap_Case: 1210; SizeArea_mm2: 8; SizeAreaWB_mm2: 14.7; SizeX_mm: 3.2; SizeY_mm: 2.5; SizeZ_mm: 2.7; AEC Category: Q200
C15 C30 C43 C45 = CMP-0007886-2: CAP, CERM, 0.1 uF, 100 V, +/- 10%, X7R, 0805; PartNumber: C2012X7R2A104K125AA; Manufacturer: TDK; Polarized: N; Value: 0.1uF; U/M: EA; Cap_F: 100nF; ESR_ohm: 0.020726; Value1: 0.020726 ohm; IRMS_A: 1.456A; TaMin_C: -55°C; TaMax_C: 125°C; Cap_Case: 0805; SizeArea_mm2: 2.5; SizeAreaWB_mm2: 6.75; SizeX_mm: 2; SizeY_mm: 1.25; SizeZ_mm: 1.45; AEC Category: Q200
C16 = CMP-0012087-3: CAP, Aluminum Polymer, 82 uF, 16 V, +/- 20%, 0.04 ohm, 8x10 SMD; Manufacturer: Panasonic; TaMin_C: -55°C; ESR_ohm: 0.04; Polarized: Y; SizeAreaWB_mm2: 113.3; Value: 82uF; TaMax_C: 105°C; SizeZ_mm: 10.2; SizeX_mm: 9; SizeY_mm: 8.3; Cap_Case: 8.3x8.3x6.9; SizeArea_mm2: 74.7; CompType: Capacitor; Cap_F: 82µF; IRMS_A: 2.12A; AEC Category: Q200
C17 = CMP-0012611-3: CAP, Tantalum Polymer, 220 uF, 10 V, +/- 20%, 0.025 ohm, 7343-30 SMD; Manufacturer: Panasonic; TaMin_C: -55°C; ESR_ohm: 0.025; Polarized: Y; SizeAreaWB_mm2: 58.59; Value: 220uF; TaMax_C: 105°C; SizeZ_mm: 3; SizeX_mm: 7.3; SizeY_mm: 4.3; SizeArea_mm2: 31.39; CompType: Capacitor; AEC Qualified: N; Cap_F: 220µF; IRMS_A: 2.4A; AEC Category: Q200
C18-C21 = CMP-0064938-2: CAP, CERM, 10 uF, 25 V,+/- 10%, X7R, 1210; Manufacturer: Wurth Elektronik; TaMin_C: -55°C; Polarized: N; SizeAreaWB_mm2: 14.7; Value1: Unknown; U/M: EA; Value: 10uF; TaMax_C: 125°C; SizeZ_mm: 2.2; SizeX_mm: 3.2; SizeY_mm: 2.5; Cap_Case: 1210; SizeArea_mm2: 8; Cap_F: 10µF; AEC Category: Q200
C22 C37 = CMP-0006833-4: CAP, CERM, 1 uF, 25 V, +/- 10%, X7R, 0603; Manufacturer: Wurth Elektronik; TaMin_C: -55°C; Polarized: N; SizeAreaWB_mm2: 4.68; Value1: Unknown; U/M: EA; Value: 1uF; TaMax_C: 125°C; SizeZ_mm: 1; SizeX_mm: 1.6; SizeY_mm: 0.8; SizeArea_mm2: 1.28; AEC Category: Q200
C25 = CMP-0007209-4: CAP, CERM, 330 pF, 50 V, +/- 5%, C0G/NP0, 0603; Manufacturer: MuRata; TaMin_C: -55°C; Polarized: N; SizeAreaWB_mm2: 4.68; Value1: Unknown; U/M: EA; Value: 330pF; TaMax_C: 125°C; SizeZ_mm: 1; SizeX_mm: 1.6; SizeY_mm: 0.8; SizeArea_mm2: 1.28; AEC Category: Q200
C33 = CMP-0007423-5: CAP, CERM, 0.047 uF, 25 V, +/- 10%, X7R, 0603; Manufacturer: MuRata; Polarized: N; SizeArea_mm2: 1.28; Value2: 25V; TaMax_C: 125°C; SizeZ_mm: 1; Value1: Unknown; SizeAreaWB_mm2: 4.68; TaMin_C: -55°C; AEC Category: Q200; SizeY_mm: 0.8; MFG_Status: TI_Obsolete; SizeX_mm: 1.6; U/M: EA
C34 = CMP-0006792-4: CAP, CERM, 56 pF, 50 V, +/- 1%, C0G/NP0, 0603; Manufacturer: AVX; TaMin_C: -55°C; Polarized: N; SizeAreaWB_mm2: 4.68; Value1: Unknown; U/M: EA; Value: 56pF; TaMax_C: 125°C; SizeZ_mm: 1; SizeX_mm: 1.6; SizeY_mm: 0.8; SizeArea_mm2: 1.28; AEC Category: Q200
C35 = CMP-0006835-4: CAP, CERM, 4700 pF, 50 V, +/- 10%, X7R, 0603; Manufacturer: Wurth Elektronik; TaMin_C: -55°C; Polarized: N; SizeAreaWB_mm2: 4.68; Value1: Unknown; U/M: EA; Value: 4700pF; TaMax_C: 125°C; SizeZ_mm: 1; SizeX_mm: 1.6; SizeY_mm: 0.8; Value2: 50V; SizeArea_mm2: 1.28; AEC Category: Q200
C36 = CMP-0006761-4: CAP, CERM, 10 pF, 50 V, +/- 5%, C0G/NP0, 0603; Manufacturer: AVX; TaMin_C: -55°C; ESR_ohm: 0.403; Polarized: N; SizeAreaWB_mm2: 4.68; Value1: 0.403 ohm; U/M: EA; Value: 10pF; TaMax_C: 125°C; SizeZ_mm: 1; SizeX_mm: 1.6; SizeY_mm: 0.8; Value2: 50V; SizeArea_mm2: 1.28; AEC Category: Q200
C38 C41 = CMP-0006832-5: CAP, CERM, 0.1 uF, 25 V, +/- 10%, X7R, 0603; Manufacturer: Wurth Elektronik; TaMin_C: -55°C; Polarized: N; SizeAreaWB_mm2: 4.68; Value1: Unknown; U/M: EA; Value: 0.1uF; TaMax_C: 125°C; SizeZ_mm: 1; SizeX_mm: 1.6; SizeY_mm: 0.8; Value2: 25V; SizeArea_mm2: 1.28; AEC Category: Q200
C39 = CMP-0006897-4: CAP, CERM, 2200 pF, 50 V, +/- 10%, X7R, 0603; Manufacturer: Kemet; TaMin_C: -55°C; Polarized: N; SizeAreaWB_mm2: 4.68; Value1: Unknown; U/M: EA; Value: 2200pF; TaMax_C: 125°C; SizeZ_mm: 1; SizeX_mm: 1.6; SizeY_mm: 0.8; SizeArea_mm2: 1.28; AEC Category: Q200
C40 = CMP-0008966-2: CAP, CERM, 3.3 uF, 25 V, +/- 10%, X7R, 1206; Manufacturer: MuRata; TaMin_C: -55°C; Polarized: N; SizeAreaWB_mm2: 10.92; Value1: Unknown; U/M: EA; Value: 3.3uF; TaMax_C: 125°C; SizeZ_mm: 1.8; SizeX_mm: 3.2; SizeY_mm: 1.6; Cap_Case: 1206; SizeArea_mm2: 5.12; Cap_F: 3.3µF; AEC Category: Q200
C42 = CMP-0064933-4: CAP, CERM, 1000 pF, 50 V,+/- 10%, X7R, 0603; Manufacturer: Wurth Elektronik; TaMin_C: -55°C; Polarized: N; SizeAreaWB_mm2: 4.68; Value1: Unknown; U/M: EA; Value: 1000pF; TaMax_C: 125°C; SizeZ_mm: 1; SizeX_mm: 1.6; SizeY_mm: 0.8; SizeArea_mm2: 1.28; AEC Category: Q200
C44 = CMP-0006737-4: CAP, CERM, 2200 pF, 100 V, +/- 10%, X7R, 0603; Manufacturer: AVX; TaMin_C: -55°C; ESR_ohm: 0.192; Polarized: N; SizeAreaWB_mm2: 4.68; Value1: 0.192 ohm; U/M: EA; Value: 2200pF; TaMax_C: 125°C; SizeZ_mm: 1; SizeX_mm: 1.6; SizeY_mm: 0.8; SizeArea_mm2: 1.28; AEC Category: Q200
D5 D6 D8 D9 D17 = CMP-0029032-2: Diode, Switching, 100 V, 0.2 A, SOD-123; Manufacturer: ON Semiconductor; Vf_V: 1V; Value: 100V; Value1: 0.2A; Io_A: 200mA; TJmax_C: 150°C; SizeAreaWB_mm2: 13.095; SizeArea_mm2: 6.545; SizeX_mm: 3.85; SizeY_mm: 1.7; SizeZ_mm: 1.35; AEC Category: Q101; Green_Lifecycle: Active; Green_REACh: Passed
D7 = CMP-0029024-2: Diode, Ultrafast, 200 V, 1 A, SMA; Manufacturer: Diodes Inc.; Vf_V: 920mV; Value: 200V; Value1: 1A; Value2: 0.92V; TJmax_C: 150°C; RJC_CperW: 25; SizeAreaWB_mm2: 37.3428; SizeArea_mm2: 16.3228; SizeX_mm: 5.59; SizeY_mm: 2.92; SizeZ_mm: 2.87; AEC Category: Q101; Green_Lifecycle: Active; Green_REACh: Passed
D12 = CMP-0005486-3: Diode, TVS, Uni, 58 V, SMA; Manufacturer: Diodes Inc.; Value1: 400W; SizeAreaWB_mm2: 37.3428; SizeArea_mm2: 16.3228; SizeX_mm: 5.59; SizeY_mm: 2.92; SizeZ_mm: 2.87; AEC Category: Q101
D18 D19 = CMP-0005751-4: Diode, Zener, 12 V, 500 mW, SOD-123; Manufacturer: Diodes Inc.; RJA_CperW: 350; SizeZ_mm: 1.35; SizeAreaWB_mm2: 13.095; AEC Category: Q101; SizeArea_mm2: 6.545; Power_W: 500mW; Value1: 0.5W; SizeY_mm: 1.7; SizeX_mm: 3.85
D20 = CMP-0005513-4: Diode, Zener, 24 V, 3 W, SMA; Manufacturer: Micro Commercial Components; SizeZ_mm: 2.87; Power_W: 3W; SizeAreaWB_mm2: 37.3428; AEC Category: Q101; SizeX_mm: 5.59; SizeArea_mm2: 16.3228; RJA_CperW: 226; SizeY_mm: 2.92
D21-D23 = CMP-0002892-3: LED, Yellow, SMD; Manufacturer: Wurth Elektronik; Value1: W; Vf_V: 2V; Type: AlInGaP; Io_A: 20mA
D25 = CMP-0028411-2: Diode, Schottky, 100 V, 3 A, SMC; Manufacturer: Diodes Inc.; SizeZ_mm: 2.6; Vf_V: 790mV; RJC_CperW: 10; Value2: 0.79V; Io_A: 3A; SizeAreaWB_mm2: 83.2686; SizeY_mm: 6.22; Green_REACh: Passed; TJmax_C: 125°C; SizeX_mm: 8.13; AEC Category: Q101; SizeArea_mm2: 50.5686; Value: 100V; Green_Lifecycle: Active
D100 = CMP-0029276-2: Diode, Super Barrier Rectifier, 60 V, 8 A, PowerDI5; Manufacturer: Diodes Inc.; TJmax_C: 175°C; RJC_CperW: 5; SizeX_mm: 6.4; Value: 60V; SizeArea_mm2: 24.96; Green_REACh: Incomplete; AEC Category: Q101; Vf_V: 620mV; SizeAreaWB_mm2: 49.56; Value2: 0.62V; SizeZ_mm: 1.05; Green_Lifecycle: Not Set; Value1: 8A; SizeY_mm: 3.9
J4 = CMP-0074913-1: Terminal Block, 3.5mm Pitch, 2x1, TH; PartNumber: ED555/2DS; Manufacturer: On-Shore Technology; Pitch_mm: 3.5; Gender: Female; Shrouded: N; Row_Count: 1; ContactFinish: Brass; Current_A: 6A; Voltage_V: 150V; Cert_CULUS: Y; CNHeader: False; CT: True; Green_Lifecycle: Active; Green_REACh: Passed
J6 J14 = CMP-0075407-2: as J7 on sheet PMP22806_RevB_SH1
J11 = CMP-0075087-1: Jumper Wire, 100mil spacing, pkg of 200, TH; Manufacturer: 3M; CNHeader: False; Green_Lifecycle: Active; Green_REACh: Passed
J15 J17 J18 = CMP-0075405-3: Header, 100mil, 2x1, Gold, TH; Manufacturer: Samtec; Current_A: 6.3A; Green_Lifecycle: Active; Pitch_mm: 2.54; Cert_CSA: Y; Cert_VDE: N; Green_REACh: Passed; Row_Count: 1; Gender: Male; Voltage_V: 550V
L3 = CMP-0063798-1: Inductor, Shielded Drum Core, Ferrite, 3.3 uH, 1.8 A, 0.055 ohm, SMD; Manufacturer: Wurth Elektronik; Isat: 1.8A @ 35% inductance drop; Irms: 1.95A @ 30C rise; Green_Lifecycle: Active; SizeAreaWB_mm2: 33.64; DCR_ohm: 0.055; Green_REACh: Passed; Value: 3.3uH; Imax_A: 1.8A; SizeZ_mm: 1.8; SizeX_mm: 4.8; SizeArea_mm2: 23.04; Ind_H: 3.3µH; AEC Category: Q200
L4 = CMP-0063890-1: Inductor, Shielded Drum Core, Ferrite, 150 nH, 30 A, 0.000235 ohm, SMD; Manufacturer: Wurth Elektronik; Isat: 32A @ 20% inductance drop; Irms: 30A @ 50C rise; Green_Lifecycle: Active; SizeAreaWB_mm2: 81; DCR_ohm: 235µ; Green_REACh: Passed; Value: 150nH; Imax_A: 30A; SizeZ_mm: 5; SizeX_mm: 7; SizeArea_mm2: 49; AEC Category: Q200
Q1 = CMP-0000326-2: Transistor, PNP, 40 V, 0.2 A, SOT-23; Manufacturer: Diodes Inc.; CompType: BJT; PNP: 1; NPN: 0; Vceo_V: 40V; Vcesat1_V: 2.5dV; Value: 40 V; IcRated_A: 2dA; Value1: 0.2 A; HfeMax: 400; TaMin_C: -55°C; TaMax_C: 150°C; U/M: EA; AEC Category: Q101; SizeArea_mm2: 7.5; SizeAreaWB_mm2: 14; SizeX_mm: 2.5; SizeY_mm: 3; SizeZ_mm: 1.1
Q2 = CMP-0001058-1: MOSFET, N-CH, 150 V, 4.6 A, PQFN08A; Alternate Manufacturer: None; Manufacturer: Fairchild Semiconductor; SizeZ_mm: 1.1; ChType: N; Value2: 11 nC; Value1: 0; VdsMax_V: 150V; SizeX_mm: 5; SizeY_mm: 6; Vgs_V: 20V; Value: 150V; Rdson45_ohm: 0.07; SizeArea_mm2: 30; AEC Category: Q101; IdsMax_A: 4.6A; SizeAreaWB_mm2: 56; U/M: EA; QgTyp_nC: 11
Q3 = CMP-0000708-1: MOSFET, N-CH, 40 V, 15 A, DQJ0008A (VSONP-8); Alternate Manufacturer: None; Manufacturer: Texas Instruments; SizeZ_mm: 1.1; ChType: N; Value2: 7.7 nC; Value1: 0.009; VdsMax_V: 40V; SizeX_mm: 6; SizeY_mm: 4.9; Vgs_V: 20V; Value: 40V; Rdson45_ohm: 9.8m; SizeArea_mm2: 29.4; AEC Category: Q101; IdsMax_A: 15A; SizeAreaWB_mm2: 55.2; U/M: EA; QgTyp_nC: 7.7
Q10 = CMP-0000589-2: MOSFET, N-CH, 30 V, 19 A, DNH0008A (VSONP-8); Alternate Manufacturer: None; Manufacturer: Texas Instruments; SizeZ_mm: 0.9; ChType: N; Value2: 13 nC; Value1: 0.006; VdsMax_V: 30V; SizeX_mm: 3.3; Vgs_V: 20V; Value: 30V; Rdson45_ohm: 6.4m; SizeArea_mm2: 10.89; AEC Category: Q101; IdsMax_A: 19A; SizeAreaWB_mm2: 18.49; QgTyp_nC: 13; ChMode: Enhancement
R11 = CMP-0025821-4: RES, 4.7, 5%, 0.1 W, AEC-Q200 Grade 0, 0603; PartNumber: CRCW06034R70JNEA; Manufacturer: Vishay-Dale; Value: 4.7; Value_Code: 4R70; Power_W: 100mW; Value2: 0.1W; VDC_V: 75V; TempCo: 200 ppm/C; SizeArea_mm2: 1.28; SizeX_mm: 1.6; SizeY_mm: 0.8; SizeZ_mm: 1; EIA_Code: E24; AEC Category: Q200; AEC Qualified: Y; AEC Grade: 0
R12 = CMP-0022458-4: RES, 4.99 k, 1%, 0.1 W, AEC-Q200 Grade 0, 0603; Manufacturer: Vishay-Dale; Power_W: 100mW; TempCo: 100 ppm/C; Value_Code: 4k99; Value: 4.99k; EIA_Code: E96; SizeX_mm: 1.6; SizeY_mm: 0.8; SizeZ_mm: 1; Value2: 0.1W; SizeArea_mm2: 1.28; CompType: Resistor; AEC Qualified: Y; VDC_V: 75V; AEC Category: Q200; AEC Grade: 0
R13 = CMP-0018666-3: RES, 39 k, 5%, 0.25 W, AEC-Q200 Grade 0, 1206; PartNumber: CRCW120639K0JNEA; Manufacturer: Vishay-Dale; Value: 39k; Value_Code: 39k0; Power_W: 250mW; Value2: 0.25W; VDC_V: 200V; TempCo: 200 ppm/C; SizeArea_mm2: 5.12; SizeX_mm: 3.2; SizeY_mm: 1.6; SizeZ_mm: 1.35; EIA_Code: E24; AEC Category: Q200; AEC Qualified: Y; AEC Grade: 0
R14 = CMP-0025821-4: RES, 4.7, 5%, 0.1 W, AEC-Q200 Grade 0, 0603; Manufacturer: Vishay-Dale; Power_W: 100mW; TempCo: 200 ppm/C; Value_Code: 4R70; Value: 4.7; EIA_Code: E24; SizeX_mm: 1.6; SizeY_mm: 0.8; SizeZ_mm: 1; Value2: 0.1W; SizeArea_mm2: 1.28; AEC Qualified: Y; VDC_V: 75V; AEC Category: Q200; AEC Grade: 0
R16 = CMP-0021831-3: RES, 3.90, 1%, 0.125 W, AEC-Q200 Grade 0, 0805; Manufacturer: Panasonic; Power_W: 125mW; TempCo: 200 ppm/C; Value_Code: 3R90; Value: 3.90; Res_ohm: 3.9; SizeX_mm: 2; SizeY_mm: 1.25; SizeZ_mm: 1.45; Value2: 0.125W; SizeArea_mm2: 2.5; AEC Qualified: Y; AEC Category: Q200; AEC Grade: 0; SizeAreaWB_mm2: 6.75
R18 = CMP-0017789-3: RES, 0.12, 1%, 0.25 W, AEC-Q200 Grade 0, 1206; Manufacturer: Panasonic; Power_W: 250mW; TempCo: 250 ppm/C; Value_Code: R390; Value: 0.12; EIA_Code: E96; Res_ohm: 0.39; SizeX_mm: 3.2; SizeY_mm: 1.6; SizeZ_mm: 1.35; Value2: 0.25W; SizeArea_mm2: 5.12; AEC Qualified: Y; AEC Category: Q200; AEC Grade: 0; SizeAreaWB_mm2: 10.92
R19 = CMP-0022895-5: RES, 1.00 k, 1%, 0.1 W, 0603; Manufacturer: Yageo; Power_W: 100mW; TempCo: 100 ppm/C; Value_Code: 1k00; Value: 1.00k; EIA_Code: E96; Res_ohm: 1k; SizeX_mm: 1.6; SizeY_mm: 0.8; SizeZ_mm: 1; Value2: 0.1W; SizeArea_mm2: 1.28; AEC Qualified: N; VDC_V: 75V; AEC Category: Q200; SizeAreaWB_mm2: 4.68
R24 = CMP-0022447-4: RES, 49.9 k, 1%, 0.1 W, AEC-Q200 Grade 0, 0603; Manufacturer: Vishay-Dale; Power_W: 100mW; TempCo: 100 ppm/C; Value_Code: 49k9; Value: 49.9k; EIA_Code: E96; SizeX_mm: 1.6; SizeY_mm: 0.8; SizeZ_mm: 1; Value2: 0.1W; SizeArea_mm2: 1.28; AEC Qualified: Y; VDC_V: 75V; AEC Category: Q200; AEC Grade: 0
R27 = CMP-0021169-3: RES, 31.6, 1%, 0.125 W, AEC-Q200 Grade 0, 0805; Manufacturer: Vishay-Dale; Power_W: 125mW; TempCo: 100 ppm/C; Value_Code: 31R6; Value: 31.6; EIA_Code: E96; SizeX_mm: 2; SizeY_mm: 1.25; SizeZ_mm: 1.45; Value2: 0.125W; SizeArea_mm2: 2.5; AEC Qualified: Y; VDC_V: 150V; AEC Category: Q200; AEC Grade: 0
R28 = CMP-0022951-5: RES, 25.5 k, 1%, 0.1 W, 0603; Manufacturer: Yageo; Power_W: 100mW; TempCo: 100 ppm/C; Value_Code: 25k5; Value: 25.5k; EIA_Code: E96; SizeX_mm: 1.6; SizeY_mm: 0.8; SizeZ_mm: 1; Value2: 0.1W; SizeArea_mm2: 1.28; AEC Qualified: N; VDC_V: 75V; AEC Category: Q200; SizeAreaWB_mm2: 4.68
R31 = CMP-0022003-4: RES, 10.0, 1%, 0.1 W, AEC-Q200 Grade 0, 0603; Manufacturer: Vishay-Dale; Power_W: 100mW; TempCo: 100 ppm/C; Value_Code: 10R0; Value: 10.0; EIA_Code: E96; Res_ohm: 10; SizeX_mm: 1.6; SizeY_mm: 0.8; SizeZ_mm: 1; Value2: 0.1W; SizeArea_mm2: 1.28; AEC Qualified: Y; VDC_V: 75V; AEC Category: Q200; AEC Grade: 0
R32 = CMP-0022008-4: RES, 110 k, 1%, 0.1 W, AEC-Q200 Grade 0, 0603; Manufacturer: Vishay-Dale; Power_W: 100mW; TempCo: 100 ppm/C; Value: 110k; EIA_Code: E96; SizeX_mm: 1.6; SizeY_mm: 0.8; SizeZ_mm: 1; Value2: 0.1W; SizeArea_mm2: 1.28; AEC Qualified: Y; VDC_V: 75V; AEC Category: Q200; AEC Grade: 0
R33 R36 R48 R59-R61 R64 R65 = CMP-0021998-4: RES, 10.0 k, 1%, 0.1 W, AEC-Q200 Grade 0, 0603; Manufacturer: Vishay-Dale; CompType: Resistor; Value: 10.0k; Res_ohm: 10k; Value_Code: 10k0; Power_W: 100mW; Value2: 0.1W; VDC_V: 75V; TempCo: 100 ppm/C; SizeArea_mm2: 1.28; SizeX_mm: 1.6; SizeY_mm: 0.8; SizeZ_mm: 1; EIA_Code: E96; AEC Category: Q200; AEC Qualified: Y; AEC Grade: 0
R34 = CMP-0025703-4: RES, 10, 5%, 0.1 W, AEC-Q200 Grade 0, 0603; Manufacturer: Vishay-Dale; Power_W: 100mW; TempCo: 200 ppm/C; Value_Code: 10R0; Value: 10; EIA_Code: E24; SizeX_mm: 1.6; SizeY_mm: 0.8; SizeZ_mm: 1; Value2: 0.1W; SizeArea_mm2: 1.28; AEC Qualified: Y; VDC_V: 75V; AEC Category: Q200; AEC Grade: 0
R35 = CMP-0022944-5: RES, 24.9 k, 1%, 0.1 W, 0603; Manufacturer: Yageo; Power_W: 100mW; TempCo: 100 ppm/C; Value_Code: 24k9; Value: 24.9k; EIA_Code: E96; SizeX_mm: 1.6; SizeY_mm: 0.8; SizeZ_mm: 1; Value2: 0.1W; SizeArea_mm2: 1.28; AEC Qualified: N; VDC_V: 75V; AEC Category: Q200; SizeAreaWB_mm2: 4.68
R37 = CMP-0021990-4: as R9 on sheet PMP22806_RevB_SH1
R38 = CMP-0022452-4: RES, 4.32 k, 1%, 0.1 W, AEC-Q200 Grade 0, 0603; Manufacturer: Vishay-Dale; Power_W: 100mW; TempCo: 100 ppm/C; Value_Code: 4k32; Value: 4.32k; EIA_Code: E96; SizeX_mm: 1.6; SizeY_mm: 0.8; SizeZ_mm: 1; Value2: 0.1W; SizeArea_mm2: 1.28; AEC Qualified: Y; VDC_V: 75V; AEC Category: Q200; AEC Grade: 0
R40 = CMP-0022931-4: RES, 237 k, 1%, 0.1 W, 0603; Manufacturer: Yageo; Power_W: 100mW; TempCo: 100 ppm/C; Value: 237k; EIA_Code: E96; SizeX_mm: 1.6; SizeY_mm: 0.8; SizeZ_mm: 1; Value2: 0.1W; SizeArea_mm2: 1.28; AEC Qualified: N; VDC_V: 75V; AEC Category: Q200; SizeAreaWB_mm2: 4.68
R41 = CMP-0020539-3: RES, 3.3 k, 5%, 0.125 W, AEC-Q200 Grade 0, 0805; Manufacturer: Vishay-Dale; Power_W: 125mW; TempCo: 200 ppm/C; Value_Code: 3k30; Value: 3.3k; EIA_Code: E24; SizeX_mm: 2; SizeY_mm: 1.25; SizeZ_mm: 1.45; Value2: 0.125W; SizeArea_mm2: 2.5; AEC Qualified: Y; VDC_V: 150V; AEC Category: Q200; AEC Grade: 0
R42 = CMP-0022532-4: RES, 60.4 k, 1%, 0.1 W, AEC-Q200 Grade 0, 0603; Manufacturer: Vishay-Dale; Power_W: 100mW; TempCo: 100 ppm/C; Value_Code: 60k4; Value: 60.4k; EIA_Code: E96; SizeX_mm: 1.6; SizeY_mm: 0.8; SizeZ_mm: 1; Value2: 0.1W; SizeArea_mm2: 1.28; AEC Qualified: Y; VDC_V: 75V; AEC Category: Q200; AEC Grade: 0
R43 = CMP-0018698-3: RES, 51, 5%, 0.25 W, AEC-Q200 Grade 0, 1206; Manufacturer: Vishay-Dale; Power_W: 250mW; TempCo: 200 ppm/C; Value_Code: 51R0; Value: 51; EIA_Code: E24; SizeX_mm: 3.2; SizeY_mm: 1.6; SizeZ_mm: 1.35; Value2: 0.25W; SizeArea_mm2: 5.12; AEC Qualified: Y; VDC_V: 200V; AEC Category: Q200; AEC Grade: 0
R47 = CMP-0022445-4: RES, 499 k, 1%, 0.1 W, AEC-Q200 Grade 0, 0603; Manufacturer: Vishay-Dale; Power_W: 100mW; TempCo: 100 ppm/C; Value: 499k; EIA_Code: E96; SizeX_mm: 1.6; SizeY_mm: 0.8; SizeZ_mm: 1; Value2: 0.1W; SizeArea_mm2: 1.28; AEC Qualified: Y; VDC_V: 75V; AEC Category: Q200; AEC Grade: 0
R55 = CMP-0025874-4: as R30 on sheet PMP22806_RevB_SH1
R68 = CMP-0022587-4: RES, 750 k, 1%, 0.1 W, AEC-Q200 Grade 0, 0603; Manufacturer: Vishay-Dale; Power_W: 100mW; TempCo: 100 ppm/C; Value: 750k; EIA_Code: E96; SizeX_mm: 1.6; SizeY_mm: 0.8; SizeZ_mm: 1; Value2: 0.1W; SizeArea_mm2: 1.28; AEC Qualified: Y; VDC_V: 75V; AEC Category: Q200; AEC Grade: 0
R69 = CMP-0016180-3: RES, 7.5, 5%, 0.75 W, AEC-Q200 Grade 0, 2010; Manufacturer: Vishay-Dale; Power_W: 750mW; TempCo: 200 ppm/C; Value_Code: 7R50; Value: 7.5; EIA_Code: E24; SizeX_mm: 5; SizeY_mm: 2.5; SizeZ_mm: 1.66; Value2: 0.75W; SizeArea_mm2: 12.5; AEC Qualified: Y; VDC_V: 400V; AEC Grade: 0; AEC Category: Q200
T2 = CMP-0087730-2: Flyback transformer for PoE applications; Manufacturer: LinkCom; SizeZ_mm: 14.5mm; ValueDisplayed: 70pF; DCR_ohm: 0.12; Ind_H: 65µH; AEC Qualified: No; Ns1toNp: 1:1:1
TP6 TP12 TP18 TP45 = CMP-0055137-1: as TP1 on sheet PMP22806_RevB_SH1
TP7 TP8 TP14 TP30 TP37 TP38 = CMP-0055138-1: as TP2 on sheet PMP22806_RevB_SH1
TP9 TP10 TP15-TP17 TP19 TP20 TP22-TP27 TP32 = CMP-0055139-1: as TP3 on sheet PMP22806_RevB_SH1
TP11 TP13 TP21 TP28 TP29 TP33 TP34 TP39 TP40 = CMP-0055140-1: as TP4 on sheet PMP22806_RevB_SH1
U1 = CMP-0089620-1: IEEE 802.3bt Type 3 Class 1-4 PoE PD with No-Opto Flyback DC-DC Controller; Manufacturer: Texas Instruments; Switching Topology: Flyback,Other; TJmax_C: +125°C; AEC Qualified: No; Number Of Outputs: 1; Standoff Height: 0mm; Switching Frequency: 250kHz; SizeZ_mm: 1mm
U2 U3 = CMP-0006165-3: Optocoupler, 5 kV, 300-600% CTR, SMT; Manufacturer: Fairchild Semiconductor; CTR (Min): 300%; CTR (Max): 600%; Voltage_Isolation_Vrms: 5kV

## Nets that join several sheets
PGND: PMP22806_RevB_SH1 (C8.2 J7.1 L5.2 R10.1), PMP22806_RevB_SH2 (34 pins)
APD: PMP22806_RevB_SH1 (J7.2 R9.1 R10.2 TP5.1), PMP22806_RevB_SH2 (U1.5)
VB: PMP22806_RevB_SH1 (J7.3), PMP22806_RevB_SH2 (C38.2 J14.1 TP20.1 U1.37)
VDD: PMP22806_RevB_SH1 (C23.1 D1.1 L6.2), PMP22806_RevB_SH2 (11 pins)
VSS: PMP22806_RevB_SH1 (C23.2 L8.2), PMP22806_RevB_SH2 (9 pins)

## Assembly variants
001: not fitted C10 C17 C24 C27 C29 C31 C34 D5 D6 D17 D18 D19 D20 L2 L4 L7 Q1 Q3 Q4 Q5 Q6 Q7 Q10 R11 R12 R15 R17 R20 R21 R22 R25 R26 R29 R31 R60 R61 R68 TP13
